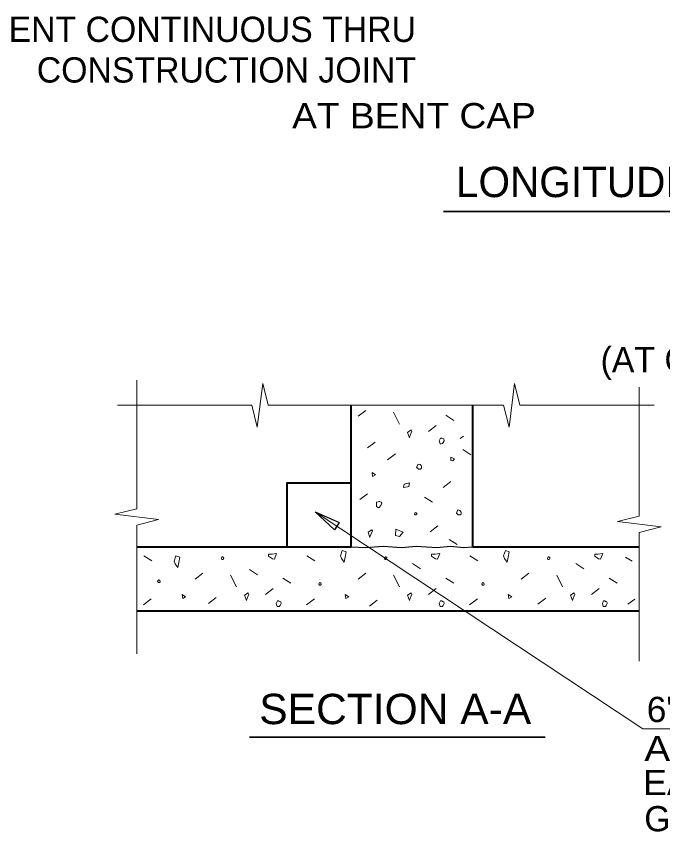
# Model space of a CAD drawing. Extents: x 0 to 34, y 0 to 23.4.
# Drawn here: x 12.45 to 16.45, y 10.5 to 15.54 of the extents above; entities that cross this region are included whole.
import ezdxf
from ezdxf.enums import TextEntityAlignment as Align

# ---------------------------------------------------------------- set-up
doc = ezdxf.new("R2010")
doc.units = 0
doc.header["$LTSCALE"] = 0.062
for name, color, linetype, lineweight in [('1', 7, 'Continuous', 40), ('4', 7, 'Continuous', 13), ('7', 7, 'Continuous', 13)]:
    doc.layers.add(name, color=color, linetype=linetype, lineweight=lineweight)

msp = doc.modelspace()

# ---------------------------------------------------------------- linework, layer by layer
at = {"layer": '1', "lineweight": 13}
for p, q in [((13.19714, 12.49849), (13.19714, 13.29406)), ((16.30542, 12.45323), (16.30542, 13.2488)), ((13.90849, 13.13755), (13.07906, 13.13755)), ((15.46578, 13.13755), (14.01005, 13.13755)), ((16.39677, 13.13755), (15.56734, 13.13755)), ((13.19714, 11.60135), (13.19714, 12.39693)), ((16.30542, 11.55609), (16.30542, 12.35167))]:
    msp.add_line(p, q, dxfattribs=at)
at = {"layer": '1'}
for p, q in [((14.52417, 12.26255), (14.52417, 13.13755)), ((15.27625, 12.26255), (15.27625, 13.13755)), ((13.19714, 12.26255), (14.52417, 12.26255)), ((15.27625, 12.26255), (16.30542, 12.26255)), ((13.19714, 11.86672), (16.30542, 11.86672))]:
    msp.add_line(p, q, dxfattribs=at)
at = {"layer": '1', "lineweight": 13}
for points in [[(13.90849, 13.13755), (13.94234, 13.00214), (13.9762, 13.27297), (14.01005, 13.13755)], [(15.46578, 13.13755), (15.49964, 13.00214), (15.53349, 13.27297), (15.56734, 13.13755)], [(13.19714, 12.49849), (13.06172, 12.46464), (13.33255, 12.43078), (13.19714, 12.39693)], [(16.30542, 12.45323), (16.17, 12.41938), (16.44083, 12.38552), (16.30542, 12.35167)]]:
    msp.add_lwpolyline(points, dxfattribs=at)
at = {"layer": '1'}
msp.add_lwpolyline([(14.12833, 12.26255), (14.12833, 12.65839), (14.52417, 12.65839)], dxfattribs=at)
at = {"layer": '1', "lineweight": 25}
msp.add_lwpolyline([(14.52417, 12.26255), (14.6126, 12.25797), (14.72052, 12.26667), (14.83542, 12.25755), (14.92594, 12.26625), (15.05302, 12.25797), (15.13661, 12.26714), (15.22016, 12.25797), (15.27625, 12.26255)], dxfattribs=at)
at = {"layer": '4', "lineweight": 35}
for p, q in [((15.0951, 14.3362), (20.11854, 14.3362)), ((13.89505, 11.08516), (15.72354, 11.08516))]:
    msp.add_line(p, q, dxfattribs=at)
at = {"layer": '4'}
msp.add_lwpolyline([(14.30089, 12.47807), (16.32745, 11.13833), (18.61932, 11.13833), (18.93219, 10.56573)], dxfattribs=at)
at = {"layer": '4', "lineweight": 25}
msp.add_lwpolyline([(14.44906, 12.41208), (14.41964, 12.3676), (14.30089, 12.47807)], close=True, dxfattribs=at)
at = {"layer": '7'}
for p, q in [((14.61427, 13.10635), (14.56615, 13.06974)), ((14.78583, 13.09526), (14.8225, 13.02172)), ((15.10969, 13.07573), (15.15917, 13.04448)), ((15.04922, 13.0126), (15.00109, 12.97599)), ((14.6726, 12.91068), (14.62448, 12.87406)), ((15.2187, 12.94719), (15.19818, 12.93156)), ((15.21391, 12.86365), (15.26339, 12.8324)), ((14.79688, 12.83672), (14.74875, 12.8001)), ((15.14063, 12.66646), (15.0925, 12.62984)), ((14.62432, 12.59), (14.57766, 12.55448)), ((14.9776, 12.57036), (15.02714, 12.53917)), ((15.05953, 12.39172), (15.01141, 12.3551)), ((15.12844, 12.30849), (15.17797, 12.27724)), ((13.24026, 12.20776), (13.28969, 12.17646)), ((14.24865, 12.20776), (14.29807, 12.17646)), ((15.25703, 12.20776), (15.30646, 12.17646)), ((16.22021, 12.19953), (16.26021, 12.17422)), ((14.90333, 12.1587), (14.95281, 12.12745)), ((15.91172, 12.1587), (15.9612, 12.12745)), ((13.60589, 12.09901), (13.55776, 12.0624)), ((13.89495, 12.12167), (13.94443, 12.09042)), ((14.61427, 12.09901), (14.56615, 12.0624)), ((15.62266, 12.09901), (15.57453, 12.0624)), ((13.77745, 12.08792), (13.81411, 12.01438)), ((14.1013, 12.06839), (14.15078, 12.03714)), ((14.78583, 12.08792), (14.8225, 12.01438)), ((15.10969, 12.06839), (15.15917, 12.03714)), ((15.79422, 12.08792), (15.83089, 12.01438)), ((16.11807, 12.06839), (16.16755, 12.03714)), ((14.04083, 12.00526), (13.99271, 11.96865)), ((15.04922, 12.00526), (15.00109, 11.96865)), ((16.0576, 12.00526), (16.00948, 11.96865)), ((13.68885, 11.94859), (13.64073, 11.91198)), ((13.28708, 11.94026), (13.23896, 11.90365)), ((14.29547, 11.94026), (14.24734, 11.90365)), ((14.68495, 11.93214), (14.63682, 11.89552)), ((15.30385, 11.94026), (15.25573, 11.90365)), ((15.72625, 11.94448), (15.67813, 11.90786)), ((16.27661, 11.93917), (16.23531, 11.90776))]:
    msp.add_line(p, q, dxfattribs=at)
for points in [[(14.87188, 12.97047), (14.88328, 12.93724), (14.88328, 12.94083), (14.89797, 12.97781), (14.89422, 12.98516)], [(15.06849, 12.91875), (15.07432, 12.90031), (15.07964, 12.90031), (15.08714, 12.90214), (15.09255, 12.9075), (15.09792, 12.91875), (15.09641, 12.92969), (15.08714, 12.93161), (15.08323, 12.93542), (15.07589, 12.93542)], [(15.14021, 12.8163), (15.13932, 12.79651), (15.15125, 12.79375), (15.16276, 12.80708)], [(14.93724, 12.77469), (14.92797, 12.75448), (14.9388, 12.74323), (14.95203, 12.74323), (14.95745, 12.74911), (14.95745, 12.7599), (14.95563, 12.76521), (14.9499, 12.77115)], [(14.65245, 12.72276), (14.65615, 12.69693), (14.67464, 12.70802)], [(14.85026, 12.65109), (14.84656, 12.62906), (14.8724, 12.63276), (14.87969, 12.63635), (14.88339, 12.65849)], [(14.67901, 12.53969), (14.67901, 12.51177), (14.69167, 12.50281), (14.69552, 12.50641), (14.70635, 12.5175), (14.71375, 12.53229), (14.70839, 12.53969), (14.70099, 12.54323), (14.6974, 12.54323), (14.69016, 12.5412)], [(14.9188, 12.47531), (14.91417, 12.46521), (14.91958, 12.45958), (14.9262, 12.45958), (14.92891, 12.4625), (14.92891, 12.46792), (14.92802, 12.47057), (14.92516, 12.47354)], [(15.18328, 12.49094), (15.17401, 12.47073), (15.18484, 12.45948), (15.19807, 12.45948), (15.20349, 12.46536), (15.20349, 12.47615), (15.20167, 12.48146), (15.19594, 12.4874)], [(14.62828, 12.3538), (14.63969, 12.32063), (14.63969, 12.32417), (14.65438, 12.3612), (14.65063, 12.36854)], [(14.79958, 12.37141), (14.79781, 12.33182), (14.82172, 12.32625), (14.84474, 12.35297)], [(13.43948, 12.20724), (13.42828, 12.17411), (13.43396, 12.15755), (13.45052, 12.13542), (13.45786, 12.1649), (13.46339, 12.19807)], [(13.72047, 12.19292), (13.72339, 12.1837), (13.72604, 12.1837), (13.72979, 12.18464), (13.7325, 12.18729), (13.73516, 12.19292), (13.73443, 12.19844), (13.72979, 12.19938), (13.72781, 12.2013), (13.72417, 12.2013)], [(14.03469, 12.21823), (14.0126, 12.21635), (14.0126, 12.20531), (14.03656, 12.1888), (14.04953, 12.18693), (14.06245, 12.22188)], [(14.46844, 12.24016), (14.45724, 12.20703), (14.46292, 12.19047), (14.47948, 12.16833), (14.48682, 12.19781), (14.49234, 12.23099)], [(14.72885, 12.19292), (14.73177, 12.1837), (14.73443, 12.1837), (14.73818, 12.18464), (14.74089, 12.18729), (14.74354, 12.19292), (14.74281, 12.19844), (14.73818, 12.19938), (14.7362, 12.2013), (14.73255, 12.2013)], [(15.04307, 12.21823), (15.02099, 12.21635), (15.02099, 12.20531), (15.04495, 12.1888), (15.05792, 12.18693), (15.07083, 12.22188)], [(15.47682, 12.24016), (15.46563, 12.20703), (15.4713, 12.19047), (15.48786, 12.16833), (15.49521, 12.19781), (15.50073, 12.23099)], [(15.73724, 12.19292), (15.74016, 12.1837), (15.74281, 12.1837), (15.74656, 12.18464), (15.74927, 12.18729), (15.75193, 12.19292), (15.7512, 12.19844), (15.74656, 12.19938), (15.74458, 12.2013), (15.74094, 12.2013)], [(16.05146, 12.21823), (16.02938, 12.21635), (16.02938, 12.20531), (16.05333, 12.1888), (16.0663, 12.18693), (16.07922, 12.22188)], [(13.33089, 12.05875), (13.32625, 12.04859), (13.33167, 12.04297), (13.33828, 12.04297), (13.34099, 12.04594), (13.34099, 12.05135), (13.3401, 12.05401), (13.33724, 12.05698)], [(14.32693, 12.04229), (14.32229, 12.03214), (14.32771, 12.02651), (14.33432, 12.02651), (14.33703, 12.02948), (14.33703, 12.0349), (14.33615, 12.03755), (14.33328, 12.04052)], [(15.33531, 12.04229), (15.33068, 12.03214), (15.33609, 12.02651), (15.34271, 12.02651), (15.34542, 12.02948), (15.34542, 12.0349), (15.34453, 12.03755), (15.34167, 12.04052)], [(13.47745, 11.96854), (13.48115, 11.94271), (13.49964, 11.9538)], [(13.86349, 11.96313), (13.8749, 11.9299), (13.8749, 11.93349), (13.88958, 11.97047), (13.88583, 11.97781)], [(14.48583, 11.96854), (14.48953, 11.94271), (14.50802, 11.9538)], [(14.87188, 11.96313), (14.88328, 11.9299), (14.88328, 11.93349), (14.89797, 11.97047), (14.89422, 11.97781)], [(15.49422, 11.96854), (15.49792, 11.94271), (15.51641, 11.9538)], [(15.88026, 11.96313), (15.89167, 11.9299), (15.89167, 11.93349), (15.90635, 11.97047), (15.9026, 11.97781)], [(14.0601, 11.91141), (14.06594, 11.89297), (14.07125, 11.89297), (14.07875, 11.89479), (14.08417, 11.90016), (14.08953, 11.91141), (14.08802, 11.92234), (14.07875, 11.92427), (14.07484, 11.92807), (14.0675, 11.92807)], [(15.06849, 11.91141), (15.07432, 11.89297), (15.07964, 11.89297), (15.08714, 11.89479), (15.09255, 11.90016), (15.09792, 11.91141), (15.09641, 11.92234), (15.08714, 11.92427), (15.08323, 11.92807), (15.07589, 11.92807)], [(16.07688, 11.91141), (16.08271, 11.89297), (16.08802, 11.89297), (16.09552, 11.89479), (16.10094, 11.90016), (16.1063, 11.91141), (16.10479, 11.92234), (16.09552, 11.92427), (16.09161, 11.92807), (16.08427, 11.92807)]]:
    msp.add_lwpolyline(points, close=True, dxfattribs=at)

# ---------------------------------------------------------------- texts
at = {"layer": '4'}
for s, p in [('REINFORCEMENT CONTINUOUS THRU', (14.92427, 15.38401)), ('CONSTRUCTION JOINT', (14.92427, 15.13297)), ("(AT CONTRACTOR'S OPTION)", (19.04349, 13.34182))]:
    msp.add_text(s, height=0.1563, dxfattribs=at).set_placement(p, align=Align.RIGHT)
for s, height, width, p in [('AT BENT CAP', 0.1563, 1.1, (14.9119, 14.85016)), ('SECTION A-A', 0.1875, 1.05, (14.79591, 11.16646))]:
    msp.add_text(s, height=height, dxfattribs=dict(at, width=width)).set_placement(p, align=Align.CENTER)
msp.add_text('LONGITUDINAL CONSTRUCTION JOINTS', height=0.1875, dxfattribs=at).set_placement((17.62299, 14.42484), align=Align.CENTER)
for s, width, p in [('6" SQUARE DRAIN', 1.05, (16.35104, 11.17911)), ('AT LOW SIDE OF', 1.15, (16.33599, 10.9376)), ('EACH BAY BETWEEN', 1.05, (16.32964, 10.7275))]:
    msp.add_text(s, height=0.1563, dxfattribs=dict(at, width=width)).set_placement(p)
msp.add_text('GIRDERS.', height=0.1563, dxfattribs=at).set_placement((16.33599, 10.50375))

doc.saveas('drawing.dxf')
